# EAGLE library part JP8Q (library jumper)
JUMPER
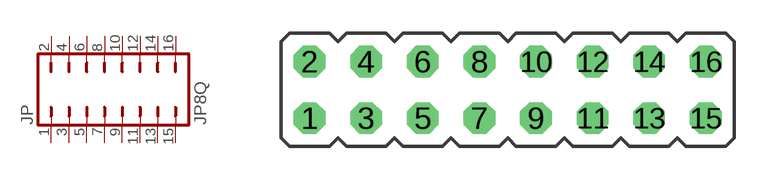
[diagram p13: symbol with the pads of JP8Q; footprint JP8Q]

Designator prefix JP

## JP8Q  [JP8Q]
1  1  pas
2  2  pas
3  3  pas
4  4  pas
5  5  pas
6  6  pas
7  7  pas
8  8  pas
9  9  pas
10  10  pas
11  11  pas
12  12  pas
13  13  pas
14  14  pas
15  15  pas
16  16  pas

## Footprint JP8Q (pad centres in mm)
JUMPER
drill 0.914 octagon: 1 -8.89,-1.27; 2 -8.89,1.27; 3 -6.35,-1.27; 4 -6.35,1.27; 5 -3.81,-1.27; 6 -3.81,1.27; 7 -1.27,-1.27; 8 -1.27,1.27; 9 1.27,-1.27; 10 1.27,1.27; 11 3.81,-1.27; 12 3.81,1.27; 13 6.35,-1.27; 14 6.35,1.27; 15 8.89,-1.27; 16 8.89,1.27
